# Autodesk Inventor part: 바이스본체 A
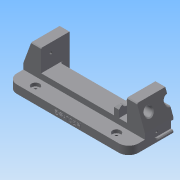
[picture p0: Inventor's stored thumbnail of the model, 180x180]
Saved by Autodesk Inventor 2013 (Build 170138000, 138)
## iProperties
Created: 2017-04
Part Number: 바이스본체 A
Material: 알루미늄 6061
Document SubType Name: Modeling
Designer: mduedu
Density: 2.71 g/cm^3
Mass: 324.199 g
Surface Area: 276.734 cm^2
Volume: 119.631 cm^3
Author: mduedu
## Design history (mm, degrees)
sketch "스케치1"
  geometry: L1 (-75, 0)-(75, 0); L2 (-75, 0)-(-75, 17); L3 (-53, 17)-(53, 17); L4 (75, 17)-(75, 0); L5 (-75, 17)-(-65.173, 44); L6 (-65.173, 44)-(-53, 44); L7 (-53, 44)-(-53, 17); L8 (0, 0)-(0, 17); L9 (75, 17)-(65.173, 44); L10 (65.173, 44)-(53, 44); L11 (53, 44)-(53, 17); 1 further point
  constraints: 22 end point, 4 perpendicular, 2 horizontal alignment, 2 midpoint, 2 symmetric about line, 1 coincident, 1 collinear, 1 horizontal, 1 vertical
  dimensions: "d0" = 150 distance of L1.start L1.end; "d1" = 17 distance of L1.start L2.end; "d2" = 27 distance of L3.start L6.end; "d3" = 22 distance of L3.start L2.end; "d4" = 70 deg angle of L3 L5; "d54" = 20 deg angle of L9 L4
extrude "돌출1" new body sketch "스케치1" stored distance "d5" = 70; taper "d6" = 0 deg
sketch "스케치2"
  geometry: L1 (0, 70)-(106, 70) reference; L2 (106, 70)-(106, 0) reference; L3 (106, 0)-(0, 0) reference; L4 (0, 47)-(106, 47); L5 (106, 47)-(106, 23); L6 (106, 23)-(0, 23); L7 (0, 23)-(0, 47); L8 (0, 70)-(0, 0) reference; 2 further points
  constraints: 8 end point, 2 parallel, 2 point on line, 1 horizontal, 1 horizontal alignment, 1 midpoint, 1 perpendicular
  dimensions: "d7" = 24 distance between parallel lines of L6 L4
extrude "돌출2" cut sketch "스케치2" stored distance "d9" = 70; taper "d10" = 0 deg
sketch "스케치3"
  geometry: L1 (22, -23)-(128, -23) reference; L2 (128, -47)-(22, -47) reference; L3 (22, -18)-(128, -18); L4 (128, -52)-(22, -52); L5 (22, -18)-(22, -52); L6 (128, -18)-(128, -52); 1 further point
  constraints: 8 end point, 3 parallel, 2 point on line, 1 perpendicular
  dimensions: "d11" = 5 distance between parallel lines of L3 L1; "d12" = 5 distance between parallel lines of L4 L2
extrude "돌출3" cut sketch "스케치3" distance "d13" = 12; taper "d14" = 0 deg
fillet "모깎기1" dims "d15" = 3, "d16" = 3
sketch "스케치4"
  geometry: L1 (103, 23)-(3, 23) reference; L2 (0, 26)-(0, 0) reference; L3 (106, 0)-(0, 0) reference; L4 (106, 26)-(106, 0) reference; L5 (96, 0)-(90, 0); L6 (90, 0)-(90, 19.5); L7 (96, 19.5)-(96, 0); L8 (90, 19.5)-(96, 19.5); A1 r 3 centre (3, 26) between (0, 26) and (3, 23) reference; A2 r 3 centre (103, 26) between (103, 23) and (106, 26) reference; 1 further point
  constraints: 8 end point, 2 perpendicular, 1 horizontal, 1 parallel, 1 point on line
  dimensions: "d17" = 10 distance between parallel lines of L7 L4; "d18" = 6 distance between parallel lines of L7 L6; "d27" = 3.5 distance between parallel lines of L8 L1
extrude "돌출4" join sketch "스케치4" distance "d19" = 12; taper "d20" = 0 deg
chamfer "모따기1" distance "d21" = 3; stored, may be unused: second distance "d22" = 2, angle "d23" = 45 deg
chamfer "모따기2" distance "d24" = 3; stored, may be unused: second distance "d25" = 2, angle "d26" = 45 deg
sketch "스케치5"
  geometry: L1 (-15.5, 35.8)-(-15.5, -25.8) reference; L2 (19.5, 0)-(0, 0) reference; C1 r 6.5 at (9.5, 15); 1 further point
  constraints: 1 centre point
  dimensions: "d28" = 13 diameter of C1; "d30" = 15 distance from line of C1.centre L2; "d31" = 25 distance from line of C1.centre L1
extrude "돌출5" cut sketch "스케치5" stored distance "d32" = 12; taper "d33" = 0 deg
sketch "스케치6"
  geometry: C1 r 5 at (-10, 15); C2 r 5 at (-60, 15); A1 r 6.5 centre (-10, 15) between (-15.766, 12) and (-4.234, 12) reference; A2 r 6.5 centre (-60, 15) between (-65.766, 12) and (-54.234, 12) reference; 1 further point
  constraints: 2 centre point, 2 coincident
  dimensions: "d34" = 10 diameter of C1; "d35" = 10 diameter of C2 (= d34)
extrude "돌출6" cut sketch "스케치6" stored distance "d36" = 12; taper "d37" = 0 deg
chamfer "모따기3" distance "d38" = 1; stored, may be unused: second distance "d39" = 2, angle "d40" = 45 deg
chamfer "모따기4" distance "d41" = 1; stored, may be unused: second distance "d42" = 2, angle "d43" = 45 deg
sketch "스케치7"
  geometry: L1 (-35, 35.8)-(-35, -25.8) reference; L2 (-70, 0)-(0, 0) reference; C1 r 5 at (-35, 15); 1 further point
  constraints: 1 centre point, 1 point on line
  dimensions: "d44" = 10 diameter of C1; "d45" = 15 distance from line of C1.centre L2
extrude "돌출7" cut sketch "스케치7" stored distance "d46" = 12; taper "d47" = 0 deg
chamfer "모따기5" distance "d48" = 1; stored, may be unused: second distance "d49" = 2, angle "d50" = 45 deg
node "작업축1"
sketch "스케치8"
  geometry: L1 (-105, 32)-(105, 32) reference; L2 (58, 32)-(64, 32); L3 (64, 32)-(64, 40); L4 (64, 40)-(58, 40); L5 (58, 40)-(58, 32); L6 (53, 38)-(53, 26) reference; 1 further point
  constraints: 8 end point, 2 parallel, 1 horizontal, 1 perpendicular, 1 point on line
  dimensions: "d51" = 5 distance from line of L6 L2.start; "d52" = 6 distance of L3.end L4.end; "d53" = 16 diameter of L4 L1
revolve "회전1" sketch "스케치8" stored, may be unused: angle "d55" = 90 deg
fillet "모깎기2"
chamfer "모따기6" distance "d56" = 1; stored, may be unused: second distance "d57" = 2, angle "d58" = 45 deg
sketch "스케치9"
  geometry: L1 (17.5, 3)-(52.5, 3); L2 (52.5, 13)-(17.5, 13); L3 (70, 0)-(0, 0) reference; L4 (17.5, 8)-(52.5, 8); A1 r 5 centre (17.5, 8) between (17.5, 13) and (17.5, 3); A2 r 5 centre (52.5, 8) between (52.5, 3) and (52.5, 13); 3 further points
  constraints: 6 end point, 4 point on circle, 3 tangent, 2 centre point, 2 midpoint, 2 parallel, 1 horizontal, 1 vertical alignment
  dimensions: "d59" = 35 distance of L4.start L4.end; "d61" = 5 radius of A2; "d62" = 8 distance between parallel lines of L3 L4
extrude "돌출8" cut sketch "스케치9" distance "d63" = 3; taper "d64" = 0 deg
chamfer "모따기7" distance "d65" = 1; stored, may be unused: second distance "d66" = 2, angle "d67" = 45 deg
chamfer "모따기8" distance "d68" = 1; stored, may be unused: second distance "d69" = 2, angle "d70" = 45 deg
feature "분할1"
sketch "스케치10"
  geometry: L1 (35, 27)-(0, 27) reference; L2 (0, 0)-(0, 27) reference; 1 further point
  dimensions: "d85" = 11.5 distance from line of point (12, 15.5) L1; "d86" = 12 distance from line of point (12, 15.5) L2
hole "구멍1" sketch "스케치10" at (12, 15.5) diameter "d71" = 3.242; stored, may be unused: countersink angle "d75" = 90 deg, drill point angle "d77" = 120 deg; dims "d72" = 6, "d73" = 4, "d74" = 2, "d76" = 8
sketch "스케치11"
  geometry: A1 r 5 centre (17.5, 8) between (17.5, 13) and (17.5, 3) reference; 1 further point
  constraints: 1 coincident
hole "구멍3" sketch "스케치11" at (17.5, 8) diameter "d78" = 2.459; stored, may be unused: countersink angle "d82" = 90 deg, drill point angle "d84" = 120 deg; dims "d79" = 4.5, "d80" = 4, "d81" = 2, "d83" = 6
sketch "스케치13"
  geometry: L1 (75, 0)-(75, 35) reference; L2 (-75, 0)-(-75, 35) reference; L3 (-75, 35)-(75, 35); L4 (75, 35)-(75, 55); L5 (75, 55)-(-75, 55); L6 (-75, 55)-(-75, 35); 1 further point
  constraints: 8 end point, 2 parallel, 1 horizontal, 1 perpendicular, 1 point on line
  dimensions: "d90" = 20 distance between parallel lines of L5 L3; "d94" = 150 distance of L4.end L5.end (derived)
extrude "돌출9" join sketch "스케치13" distance "d92" = 10; taper "d93" = 0 deg
sketch "스케치14"
  geometry: L1 (-75, -35)-(-75, -55) reference; L2 (75, -55)-(75, -35) reference; L3 (-75, -45)-(75, -45); 3 further points
  constraints: 2 end point, 2 midpoint, 2 point on line
  dimensions: "d95" = 50 horizontal distance of point (-50, -45) point (0, 0); "d96" = 100 distance of point (50, -45) point (-50, -45)
fillet "모깎기3" dims "d97" = 12
chamfer "모따기9" distance "d98" = 1; stored, may be unused: second distance "d99" = 2, angle "d100" = 45 deg
hole "구멍4" sketch "스케치14" diameter "d101" = 4.134; stored, may be unused: countersink angle "d105" = 90 deg, drill point angle "d107" = 118 deg; dims "d102" = 6, "d103" = 10, "d104" = 4, "d106" = 8
sketch "스케치15"
  geometry: L1 (0, 0)-(126, 0) reference; 3 further points
  constraints: 1 midpoint, 1 vertical alignment, 1 other
  dimensions: "d109" = 5 distance from line of point (63, 5) L1
feature "엠보싱2" sketch "스케치15" dims "d0" = 150, "d1" = 17, "d2" = 27, "d3" = 22, "d4" = 70 deg, "d54" = 20 deg, "d110" = 0.5, "d111" = 0
node "솔리드1"
mirror "대칭1"
mirror "대칭2"
mirror "대칭3"
mirror "대칭4"
node "투영된 루프1"
